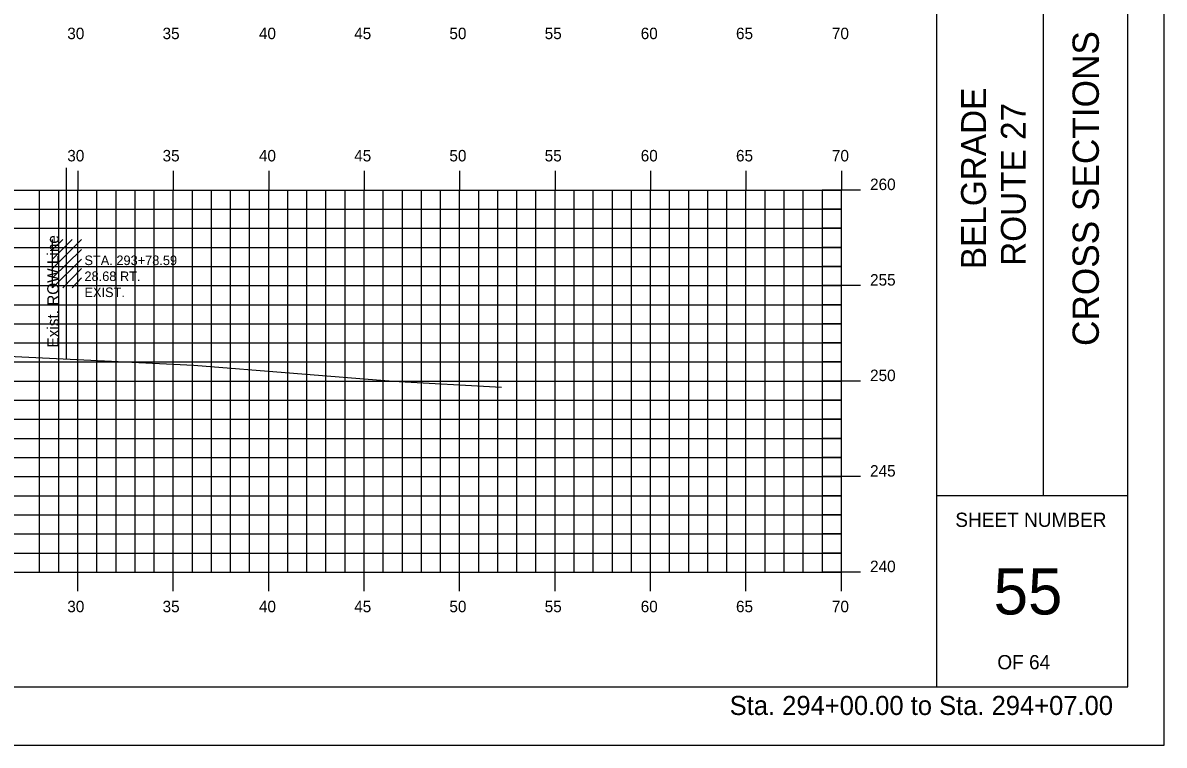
# Model space of a CAD drawing. Extents: x 859129 to 859299, y 366268 to 366378.
# Drawn here: x 859239.6 to 859299.4, y 366268.2 to 366306 of the extents above; entities that cross this region are included whole.
import ezdxf

# ---------------------------------------------------------------- set-up
doc = ezdxf.new("R2010")
doc.units = 0
for name, color, linetype in [('BORDER', 7, 'Continuous'), ('D_Text_Monospaced', 7, 'Continuous'), ('E_ROW_Line', 7, 'Continuous'), ('H_V ANNOTATION', 7, 'Continuous'), ('HIGHWAY_TITLE', 7, 'Continuous'), ('MAJOR', 7, 'Continuous'), ('MINOR', 7, 'Continuous'), ('PLOT BOUNDARY', 7, 'Continuous'), ('S_Buildings_SillElevation', 7, 'Continuous'), ('S_Roadway_Centerline', 7, 'Continuous')]:
    doc.layers.add(name, color=color, linetype=linetype)

msp = doc.modelspace()

# ---------------------------------------------------------------- linework, layer by layer
at = {"layer": 'BORDER'}
for p, q in [((859287.462, 366271.236), (859287.462, 366376.239)), ((859297.462, 366271.236), (859297.462, 366376.236)), ((859293.053, 366281.239), (859293.053, 366316.239)), ((859287.462, 366281.239), (859297.462, 366281.239)), ((859137.462, 366271.236), (859297.462, 366271.236))]:
    msp.add_line(p, q, dxfattribs=at)
at = {"layer": 'E_ROW_Line'}
msp.add_line((859241.861, 366288.392), (859241.861, 366298.392), dxfattribs=at)
at = {"layer": 'MAJOR'}
for p, q in [((859242.462, 366298.238), (859242.462, 366297.236)), ((859247.462, 366298.238), (859247.462, 366297.236)), ((859252.462, 366298.238), (859252.462, 366297.236)), ((859257.462, 366298.238), (859257.462, 366297.236)), ((859262.462, 366298.238), (859262.462, 366297.236)), ((859267.462, 366298.238), (859267.462, 366297.236)), ((859272.462, 366298.238), (859272.462, 366297.236)), ((859277.462, 366298.238), (859277.462, 366297.236)), ((859282.462, 366298.238), (859282.462, 366297.236)), ((859142.462, 366297.236), (859282.462, 366297.236)), ((859142.462, 366297.236), (859282.462, 366297.236)), ((859242.462, 366277.236), (859242.462, 366297.236)), ((859247.462, 366277.236), (859247.462, 366297.236)), ((859252.462, 366277.236), (859252.462, 366297.236)), ((859257.462, 366277.236), (859257.462, 366297.236)), ((859262.462, 366277.236), (859262.462, 366297.236)), ((859267.462, 366277.236), (859267.462, 366297.236)), ((859272.462, 366277.236), (859272.462, 366297.236)), ((859277.462, 366277.236), (859277.462, 366297.236)), ((859283.464, 366297.236), (859281.46, 366297.236)), ((859282.462, 366277.236), (859282.462, 366297.236)), ((859282.462, 366277.236), (859282.462, 366297.236)), ((859142.462, 366292.236), (859282.462, 366292.236)), ((859283.464, 366292.236), (859281.46, 366292.236)), ((859142.462, 366287.236), (859282.462, 366287.236)), ((859283.464, 366287.236), (859281.46, 366287.236)), ((859142.462, 366282.236), (859282.462, 366282.236)), ((859283.464, 366282.236), (859281.46, 366282.236)), ((859142.462, 366277.236), (859282.462, 366277.236)), ((859142.462, 366277.236), (859282.462, 366277.236)), ((859242.462, 366276.234), (859242.462, 366277.236)), ((859247.462, 366276.234), (859247.462, 366277.236)), ((859252.462, 366276.234), (859252.462, 366277.236)), ((859257.462, 366276.234), (859257.462, 366277.236)), ((859262.462, 366276.234), (859262.462, 366277.236)), ((859267.462, 366276.234), (859267.462, 366277.236)), ((859272.462, 366276.234), (859272.462, 366277.236)), ((859277.462, 366276.234), (859277.462, 366277.236)), ((859283.464, 366277.236), (859281.46, 366277.236)), ((859282.462, 366276.234), (859282.462, 366277.236))]:
    msp.add_line(p, q, dxfattribs=at)
at = {"layer": 'MINOR'}
for p, q in [((859240.462, 366277.236), (859240.462, 366297.236)), ((859241.462, 366277.236), (859241.462, 366297.236)), ((859243.462, 366277.236), (859243.462, 366297.236)), ((859244.462, 366277.236), (859244.462, 366297.236)), ((859245.462, 366277.236), (859245.462, 366297.236)), ((859246.462, 366277.236), (859246.462, 366297.236)), ((859248.462, 366277.236), (859248.462, 366297.236)), ((859249.462, 366277.236), (859249.462, 366297.236)), ((859250.462, 366277.236), (859250.462, 366297.236)), ((859251.462, 366277.236), (859251.462, 366297.236)), ((859253.462, 366277.236), (859253.462, 366297.236)), ((859254.462, 366277.236), (859254.462, 366297.236)), ((859255.462, 366277.236), (859255.462, 366297.236)), ((859256.462, 366277.236), (859256.462, 366297.236)), ((859258.462, 366277.236), (859258.462, 366297.236)), ((859259.462, 366277.236), (859259.462, 366297.236)), ((859260.462, 366277.236), (859260.462, 366297.236)), ((859261.462, 366277.236), (859261.462, 366297.236)), ((859263.462, 366277.236), (859263.462, 366297.236)), ((859264.462, 366277.236), (859264.462, 366297.236)), ((859265.462, 366277.236), (859265.462, 366297.236)), ((859266.462, 366277.236), (859266.462, 366297.236)), ((859268.462, 366277.236), (859268.462, 366297.236)), ((859269.462, 366277.236), (859269.462, 366297.236)), ((859270.462, 366277.236), (859270.462, 366297.236)), ((859271.462, 366277.236), (859271.462, 366297.236)), ((859273.462, 366277.236), (859273.462, 366297.236)), ((859274.462, 366277.236), (859274.462, 366297.236)), ((859275.462, 366277.236), (859275.462, 366297.236)), ((859276.462, 366277.236), (859276.462, 366297.236)), ((859278.462, 366277.236), (859278.462, 366297.236)), ((859279.462, 366277.236), (859279.462, 366297.236)), ((859280.462, 366277.236), (859280.462, 366297.236)), ((859281.462, 366277.236), (859281.462, 366297.236)), ((859142.462, 366296.236), (859282.462, 366296.236)), ((859282.462, 366296.236), (859281.46, 366296.236)), ((859142.462, 366295.236), (859282.462, 366295.236)), ((859282.462, 366295.236), (859281.46, 366295.236)), ((859142.462, 366294.236), (859282.462, 366294.236)), ((859282.462, 366294.236), (859281.46, 366294.236)), ((859142.462, 366293.236), (859282.462, 366293.236)), ((859282.462, 366293.236), (859281.46, 366293.236)), ((859142.462, 366291.236), (859282.462, 366291.236)), ((859282.462, 366291.236), (859281.46, 366291.236)), ((859142.462, 366290.236), (859282.462, 366290.236)), ((859282.462, 366290.236), (859281.46, 366290.236)), ((859142.462, 366289.236), (859282.462, 366289.236)), ((859282.462, 366289.236), (859281.46, 366289.236)), ((859142.462, 366288.236), (859282.462, 366288.236)), ((859282.462, 366288.236), (859281.46, 366288.236)), ((859142.462, 366286.236), (859282.462, 366286.236)), ((859282.462, 366286.236), (859281.46, 366286.236)), ((859142.462, 366285.236), (859282.462, 366285.236)), ((859282.462, 366285.236), (859281.46, 366285.236)), ((859142.462, 366284.236), (859282.462, 366284.236)), ((859282.462, 366284.236), (859281.46, 366284.236)), ((859142.462, 366283.236), (859282.462, 366283.236)), ((859282.462, 366283.236), (859281.46, 366283.236)), ((859142.462, 366281.236), (859282.462, 366281.236)), ((859282.462, 366281.236), (859281.46, 366281.236)), ((859142.462, 366280.236), (859282.462, 366280.236)), ((859282.462, 366280.236), (859281.46, 366280.236)), ((859142.462, 366279.236), (859282.462, 366279.236)), ((859282.462, 366279.236), (859281.46, 366279.236)), ((859142.462, 366278.236), (859282.462, 366278.236)), ((859282.462, 366278.236), (859281.46, 366278.236))]:
    msp.add_line(p, q, dxfattribs=at)
at = {"layer": 'PLOT BOUNDARY'}
msp.add_lwpolyline([(859129.368, 366268.177), (859299.368, 366268.177), (859299.368, 366378.177), (859129.368, 366378.177)], close=True, dxfattribs=at)
at = {"layer": 'S_Buildings_SillElevation'}
for p, q in [((859241.144, 366292.117), (859241.144, 366294.644)), ((859241.144, 366293.134), (859242.653, 366294.644)), ((859241.144, 366293.626), (859242.161, 366294.644)), ((859241.144, 366294.119), (859241.669, 366294.644)), ((859241.144, 366292.642), (859242.653, 366294.119)), ((859241.144, 366292.117), (859242.653, 366293.626)), ((859241.669, 366292.117), (859242.653, 366293.134)), ((859242.161, 366292.117), (859242.653, 366292.642))]:
    msp.add_line(p, q, dxfattribs=at)
at = {"layer": 'S_Roadway_Centerline'}
msp.add_lwpolyline([(859169.906, 366286.981), (859171.66, 366286.936), (859172.507, 366286.988), (859185.297, 366287.368), (859188.748, 366287.629), (859194.777, 366288.061), (859197.182, 366288.265), (859197.292, 366288.264), (859198.102, 366288.284), (859201.989, 366288.376), (859206.239, 366288.411), (859213.208, 366288.504), (859217.392, 366288.393), (859222.394, 366288.312), (859223.589, 366288.339), (859225, 366288.313), (859225.461, 366288.398), (859225.72, 366288.403), (859227.504, 366288.671), (859228.402, 366288.793), (859238.08, 366288.573), (859248.539, 366288.071), (859258.988, 366287.239), (859264.658, 366286.917)], dxfattribs=at)

# ---------------------------------------------------------------- texts
at = {"layer": 'BORDER'}
for s, height, rotation, p in [('CROSS SECTIONS', 1.37787, 90, (859295.946, 366289.073)), ('SHEET NUMBER', 0.74527, 360, (859288.427, 366279.603)), ('55', 2.4194, 360, (859290.437, 366275.019)), ('OF 64', 0.7453, 360, (859290.629, 366272.149))]:
    msp.add_text(s, height=height, rotation=rotation, dxfattribs=at).set_placement(p)
at = {"layer": 'D_Text_Monospaced'}
for s, height, p in [('STA. 293+78.59', 0.49998, (859242.81, 366293.308)), ('28.68 RT.', 0.5, (859242.81, 366292.474)), ('EXIST. ', 0.5, (859242.81, 366291.634))]:
    msp.add_text(s, height=height, dxfattribs=at).set_placement(p)
at = {"layer": 'E_ROW_Line'}
msp.add_text('Exist. ROW Line', height=0.6, rotation=90, dxfattribs=at).set_placement((859241.461, 366288.992))
at = {"layer": 'H_V ANNOTATION'}
for s, height, p in [('30', 0.6, (859241.91, 366305.136)), ('35', 0.6, (859246.902, 366305.136)), ('40', 0.6, (859251.948, 366305.136)), ('45', 0.6, (859256.94, 366305.136)), ('50', 0.6, (859261.926, 366305.136)), ('55', 0.6, (859266.918, 366305.136)), ('60', 0.6, (859271.948, 366305.136)), ('65', 0.6, (859276.94, 366305.136)), ('70', 0.6, (859281.964, 366305.136)), ('30', 0.6, (859241.91, 366298.736)), ('35', 0.6, (859246.902, 366298.736)), ('40', 0.6, (859251.948, 366298.736)), ('45', 0.6, (859256.94, 366298.736)), ('50', 0.6, (859261.926, 366298.736)), ('55', 0.6, (859266.918, 366298.736)), ('60', 0.6, (859271.948, 366298.736)), ('65', 0.6, (859276.94, 366298.736)), ('70', 0.6, (859281.964, 366298.736)), ('260', 0.6, (859283.962, 366297.236)), ('255', 0.6, (859283.962, 366292.236)), ('250', 0.6, (859283.962, 366287.236)), ('245', 0.6, (859283.962, 366282.236)), ('240', 0.6, (859283.962, 366277.236)), ('30', 0.6, (859241.91, 366275.136)), ('35', 0.6, (859246.902, 366275.136)), ('40', 0.6, (859251.948, 366275.136)), ('45', 0.6, (859256.94, 366275.136)), ('50', 0.6, (859261.926, 366275.136)), ('55', 0.6, (859266.918, 366275.136)), ('60', 0.6, (859271.948, 366275.136)), ('65', 0.6, (859276.94, 366275.136)), ('70', 0.6, (859281.964, 366275.136)), ('Sta. 294+00.00 to Sta. 294+07.00', 1.0002, (859276.608, 366269.756))]:
    msp.add_text(s, height=height, dxfattribs=at).set_placement(p)
at = {"layer": 'HIGHWAY_TITLE'}
for s, p in [('BELGRADE', (859290.034, 366293.095)), ('ROUTE 27', (859292.121, 366293.269))]:
    msp.add_text(s, height=1.3043, rotation=90, dxfattribs=at).set_placement(p)

doc.saveas('drawing.dxf')
